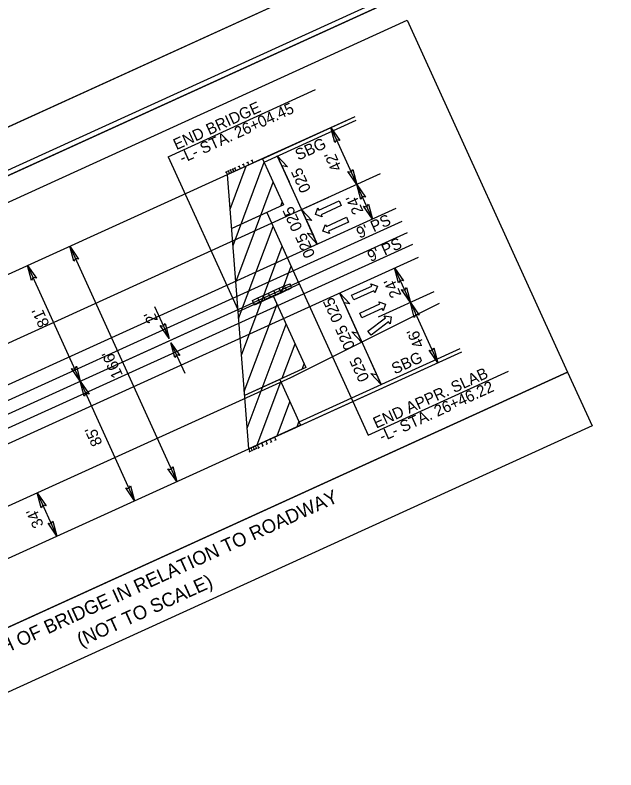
# Model space of a CAD drawing. Extents: x 2247864 to 2249896, y 662531 to 664296.
# Drawn here: x 2248887 to 2249194.5, y 663642.7 to 664028.8 of the extents above; entities that cross this region are included whole.
import ezdxf

# ---------------------------------------------------------------- set-up
doc = ezdxf.new("R2010")
doc.units = 0
for name, color, linetype in [('Prop Approach Slab', 7, 'Continuous'), ('Prop Approach Slab Hatching', 7, 'Continuous'), ('Prop Conc Barrier', 7, 'Continuous'), ('Prop Conc Shoulder Berm Gutter', 7, 'Continuous'), ('Prop Dimension', 7, 'Continuous'), ('Prop Dimension Text', 7, 'Continuous'), ('Prop EOT', 7, 'Continuous'), ('Prop Guardrail', 7, 'Continuous'), ('Prop Guardrail Attenuator CELL', 7, 'Continuous'), ('Prop Horizontal Alignment', 7, 'Continuous'), ('Prop Lane Arrow CELL', 7, 'Continuous'), ('Prop Lane Lines', 7, 'Continuous'), ('Prop Paved Shoulder', 7, 'Continuous'), ('Prop Roadway Bridge', 7, 'Continuous'), ('Prop Structure Anchor Unit CELL', 7, 'Continuous'), ('Prop Superelevation  Arrow CELL', 7, 'Continuous'), ('Prop Superelevation Label', 7, 'Continuous'), ('Prop Terminator CELL', 7, 'Continuous'), ('Sheet Clip Boundary CELL', 7, 'Continuous'), ('Sheet Cutting Line CELL', 7, 'Continuous'), ('Sheet Layout Plan Border', 7, 'Continuous'), ('Sheet Plan CELL', 7, 'Continuous'), ('Sheet Plan Layout CELL', 7, 'Continuous'), ('Sheet Plot Border Inside CELL', 7, 'Continuous'), ('Sheet Plot Border Outside CELL', 7, 'Continuous')]:
    doc.layers.add(name, color=color, linetype=linetype)

msp = doc.modelspace()

# ---------------------------------------------------------------- linework, layer by layer
at = {"layer": 'Prop Approach Slab'}
for p, q in [((2249013.7, 663955.37), (2248995.74, 663947.21)), ((2249013.66, 663955.35), (2249024.38, 663931.77)), ((2249024.38, 663931.77), (2248997.87, 663919.73)), ((2249015.83, 663927.89), (2248997.87, 663919.73)), ((2249015.83, 663927.89), (2249032.48, 663891.24)), ((2249032.48, 663891.24), (2249001.17, 663877.02)), ((2249019.14, 663885.18), (2249001.17, 663877.02)), ((2249019.14, 663885.18), (2249035.79, 663848.53)), ((2249035.79, 663848.53), (2249004.48, 663834.31)), ((2249022.45, 663842.47), (2249004.48, 663834.31)), ((2249022.45, 663842.47), (2249033.11, 663819)), ((2249033.11, 663819), (2249006.6, 663806.96))]:
    msp.add_line(p, q, dxfattribs=at)
at = {"layer": 'Prop Approach Slab Hatching'}
for p, q in [((2248998.55, 663910.88), (2249014.5, 663953.52)), ((2248997.11, 663929.55), (2249005.34, 663951.57)), ((2249000, 663892.21), (2249019.12, 663943.35)), ((2249022.98, 663931.13), (2249023.74, 663933.17)), ((2249001.44, 663873.55), (2249019.08, 663920.72)), ((2249002.89, 663854.88), (2249023.71, 663910.55)), ((2249023.36, 663887.1), (2249028.33, 663900.38)), ((2249004.34, 663836.21), (2249021.06, 663880.95)), ((2249005.78, 663817.55), (2249025.68, 663870.77)), ((2249023.75, 663843.07), (2249030.31, 663860.6)), ((2249033.9, 663847.68), (2249034.93, 663850.42)), ((2249010.99, 663808.95), (2249023.04, 663841.17)), ((2249021.14, 663813.56), (2249027.66, 663830.99)), ((2249031.3, 663818.17), (2249032.28, 663820.82))]:
    msp.add_line(p, q, dxfattribs=at)
at = {"layer": 'Prop Conc Barrier'}
msp.add_line((2248812.36, 663792.42), (2249009.02, 663881.76), dxfattribs=at)
at = {"layer": 'Prop Conc Shoulder Berm Gutter'}
for p, q in [((2249014.42, 663953.67), (2249061.56, 663975.15)), ((2249032.35, 663820.68), (2249114.82, 663858.27))]:
    msp.add_line(p, q, dxfattribs=at)
at = {"layer": 'Prop Dimension'}
for p, q in [((2249048.67, 663971.26), (2249061.88, 663942.18)), ((2249069.91, 663924.51), (2249061.88, 663942.18)), ((2248915.05, 663910.56), (2248969.73, 663790.2)), ((2248893.47, 663900.75), (2248920.39, 663841.5)), ((2249089.3, 663881.83), (2249081.27, 663899.49)), ((2248958.42, 663879.73), (2248965.81, 663863.46)), ((2249089.3, 663881.83), (2249103.35, 663850.9)), ((2249017.2, 663870.38), (2249017.21, 663870.38)), ((2248966.81, 663861.25), (2248973.93, 663845.59)), ((2248920.39, 663841.5), (2248948.14, 663780.4)), ((2249029.24, 663843.88), (2249029.25, 663843.88)), ((2248898.36, 663784.42), (2248908.39, 663762.34))]:
    msp.add_line(p, q, dxfattribs=at)
at = {"layer": 'Prop Dimension Text'}
for p, q in [((2248660.85, 663831.67), (2249087.72, 664026.19)), ((2249087.72, 664026.19), (2249169.78, 663846.12)), ((2248965.43, 663956.4), (2249040.76, 663990.73)), ((2248965.43, 663956.4), (2249001.09, 663878.15)), ((2249031.32, 663928.3), (2249047.63, 663935.73)), ((2249032.04, 663892.21), (2249067.69, 663813.97)), ((2249169.78, 663846.12), (2248742.91, 663651.6)), ((2249067.69, 663813.97), (2249139.51, 663846.69))]:
    msp.add_line(p, q, dxfattribs=at)
msp.add_lwpolyline([(2248742.91, 663651.6), (2249169.78, 663846.12), (2249182.27, 663818.71), (2248755.39, 663624.19)], close=True, dxfattribs=at)
at = {"layer": 'Prop EOT'}
for p, q in [((2248794.68, 663820.8), (2249074.06, 663947.71)), ((2248734.68, 663772.23), (2249082.11, 663930.06)), ((2248746.08, 663747.22), (2249093.51, 663905.04)), ((2249028.21, 663843.41), (2249104.25, 663881.48)), ((2248758.15, 663720.73), (2249028.21, 663843.41))]:
    msp.add_line(p, q, dxfattribs=at)
at = {"layer": 'Prop Guardrail'}
for p, q in [((2249060.82, 663976.77), (2249008.88, 663953.18)), ((2249019.75, 663812.93), (2249115.63, 663856.48))]:
    msp.add_line(p, q, dxfattribs=at)
at = {"layer": 'Prop Guardrail Attenuator CELL'}
for p, q in [((2249024.89, 663890.34), (2249025.8, 663890.75)), ((2249025.8, 663890.75), (2249027.73, 663891.35)), ((2249028.14, 663890.44), (2249027.73, 663891.35)), ((2249013.97, 663885.38), (2249016.7, 663886.62)), ((2249016.7, 663886.62), (2249019.43, 663887.86)), ((2249017.73, 663884.34), (2249016.7, 663886.62)), ((2249019.43, 663887.86), (2249022.16, 663889.1)), ((2249020.46, 663885.58), (2249019.43, 663887.86)), ((2249020.46, 663885.58), (2249023.19, 663886.82)), ((2249022.16, 663889.1), (2249024.89, 663890.34)), ((2249023.19, 663886.82), (2249022.16, 663889.1)), ((2249023.19, 663886.82), (2249025.93, 663888.07)), ((2249025.93, 663888.07), (2249024.89, 663890.34)), ((2249025.93, 663888.07), (2249026.84, 663888.48)), ((2249026.84, 663888.48), (2249028.55, 663889.53)), ((2249028.55, 663889.53), (2249028.14, 663890.44)), ((2249008.5, 663882.9), (2249011.24, 663884.14)), ((2249009.54, 663880.62), (2249008.5, 663882.9)), ((2249011.24, 663884.14), (2249013.97, 663885.38)), ((2249012.27, 663881.86), (2249011.24, 663884.14)), ((2249012.27, 663881.86), (2249015, 663883.1)), ((2249015, 663883.1), (2249013.97, 663885.38)), ((2249015, 663883.1), (2249017.73, 663884.34)), ((2249017.73, 663884.34), (2249020.46, 663885.58)), ((2249009.54, 663880.62), (2249012.27, 663881.86))]:
    msp.add_line(p, q, dxfattribs=at)
at = {"layer": 'Prop Horizontal Alignment'}
msp.add_line((2248740.38, 663759.73), (2249087.81, 663917.55), dxfattribs=at)
at = {"layer": 'Prop Lane Arrow CELL'}
for p, q in [((2249042.49, 663929.1), (2249052.79, 663933.8)), ((2249052.79, 663933.8), (2249053.89, 663931.37)), ((2249040.74, 663926.8), (2249041.98, 663930.21)), ((2249041.98, 663930.21), (2249042.49, 663929.1)), ((2249053.89, 663931.37), (2249043.59, 663926.68)), ((2249044.1, 663925.57), (2249040.74, 663926.8)), ((2249043.59, 663926.68), (2249044.1, 663925.57)), ((2249046.33, 663920.68), (2249056.63, 663925.37)), ((2249056.63, 663925.37), (2249057.73, 663922.95)), ((2249044.58, 663918.37), (2249045.82, 663921.78)), ((2249045.82, 663921.78), (2249046.33, 663920.68)), ((2249057.73, 663922.95), (2249047.43, 663918.25)), ((2249047.94, 663917.15), (2249044.58, 663918.37)), ((2249047.43, 663918.25), (2249047.94, 663917.15)), ((2249069.56, 663890.21), (2249069.06, 663891.31)), ((2249069.06, 663891.31), (2249072.42, 663890.09)), ((2249059.26, 663885.51), (2249069.56, 663890.21)), ((2249070.67, 663887.78), (2249060.37, 663883.09)), ((2249071.17, 663886.68), (2249070.67, 663887.78)), ((2249072.42, 663890.09), (2249071.17, 663886.68)), ((2249060.37, 663883.09), (2249059.26, 663885.51)), ((2249063.4, 663876.42), (2249073.7, 663881.12)), ((2249073.7, 663881.12), (2249073.2, 663882.22)), ((2249073.2, 663882.22), (2249076.56, 663881)), ((2249076.56, 663881), (2249075.31, 663877.58)), ((2249064.51, 663874), (2249063.4, 663876.42)), ((2249074.81, 663878.69), (2249064.51, 663874)), ((2249075.31, 663877.58), (2249074.81, 663878.69)), ((2249067.57, 663867.15), (2249076.58, 663873.99)), ((2249078.2, 663871.87), (2249069.18, 663865.03)), ((2249076.58, 663873.99), (2249075.85, 663874.96)), ((2249075.85, 663874.96), (2249079.4, 663874.5)), ((2249078.93, 663870.9), (2249078.2, 663871.87)), ((2249079.4, 663874.5), (2249078.93, 663870.9)), ((2249069.18, 663865.03), (2249067.57, 663867.15))]:
    msp.add_line(p, q, dxfattribs=at)
at = {"layer": 'Prop Lane Lines'}
msp.add_line((2249073.03, 663874.43), (2249101.55, 663887.38), dxfattribs=at)
at = {"layer": 'Prop Paved Shoulder'}
for p, q in [((2249013.66, 663955.35), (2249060.8, 663976.83)), ((2248737.69, 663765.61), (2249085.12, 663923.43)), ((2248743.07, 663753.84), (2249090.5, 663911.67)), ((2249025.01, 663815.32), (2249115.59, 663856.59))]:
    msp.add_line(p, q, dxfattribs=at)
at = {"layer": 'Prop Roadway Bridge'}
for p, q in [((2248815.39, 663865.29), (2248995.74, 663947.21)), ((2249006.6, 663806.96), (2248995.74, 663947.21)), ((2248826.26, 663725.03), (2249006.6, 663806.96))]:
    msp.add_line(p, q, dxfattribs=at)
at = {"layer": 'Prop Structure Anchor Unit CELL'}
for p, q in [((2248995.74, 663947.21), (2249008.88, 663953.18)), ((2249003.46, 663952.41), (2249004.26, 663952.77)), ((2249004.5, 663951.19), (2249003.86, 663952.59)), ((2249005.65, 663953.4), (2249006.46, 663953.77)), ((2249006.69, 663952.18), (2249006.05, 663953.59)), ((2249007.84, 663954.4), (2249008.65, 663954.76)), ((2249008.88, 663953.18), (2249008.24, 663954.58)), ((2248994.7, 663948.43), (2248995.5, 663948.79)), ((2248995.74, 663947.21), (2248995.1, 663948.61)), ((2248995.79, 663948.93), (2248996.6, 663949.29)), ((2248996.83, 663947.71), (2248996.2, 663949.11)), ((2248996.89, 663949.42), (2248997.69, 663949.79)), ((2248997.93, 663948.2), (2248997.29, 663949.61)), ((2248997.98, 663949.92), (2248998.79, 663950.29)), ((2248999.02, 663948.7), (2248998.39, 663950.1)), ((2248999.08, 663950.42), (2248999.88, 663950.78)), ((2249000.12, 663949.2), (2248999.48, 663950.6)), ((2249001.27, 663951.41), (2249002.07, 663951.78)), ((2249002.31, 663950.19), (2249001.67, 663951.6)), ((2249006.6, 663806.96), (2249019.75, 663812.93)), ((2249013.18, 663809.94), (2249013.81, 663808.54)), ((2249015.37, 663810.94), (2249016, 663809.53)), ((2249015.6, 663809.35), (2249016.4, 663809.72)), ((2249017.56, 663811.93), (2249018.19, 663810.53)), ((2249017.79, 663810.35), (2249018.6, 663810.71)), ((2249019.75, 663812.93), (2249020.38, 663811.52)), ((2249019.98, 663811.34), (2249020.79, 663811.71)), ((2249006.6, 663806.96), (2249007.24, 663805.55)), ((2249006.84, 663805.37), (2249007.64, 663805.74)), ((2249007.7, 663807.45), (2249008.34, 663806.05)), ((2249007.93, 663805.87), (2249008.74, 663806.23)), ((2249008.79, 663807.95), (2249009.43, 663806.55)), ((2249009.03, 663806.37), (2249009.83, 663806.73)), ((2249009.89, 663808.45), (2249010.53, 663807.05)), ((2249010.12, 663806.86), (2249010.93, 663807.23)), ((2249010.98, 663808.95), (2249011.62, 663807.54)), ((2249011.22, 663807.36), (2249012.02, 663807.73)), ((2249013.41, 663808.36), (2249014.21, 663808.72))]:
    msp.add_line(p, q, dxfattribs=at)
at = {"layer": 'Prop Superelevation  Arrow CELL'}
for p, q in [((2249021.19, 663956.76), (2249027.23, 663943.51)), ((2249033.64, 663929.36), (2249039.67, 663916.12)), ((2249041.66, 663911.69), (2249035.63, 663924.93)), ((2249053.06, 663886.68), (2249059.09, 663873.44)), ((2249064.64, 663861.19), (2249058.6, 663874.43)), ((2249074.34, 663839.82), (2249068.31, 663853.07))]:
    msp.add_line(p, q, dxfattribs=at)
for points in [[(2249021.19, 663956.76), (2249026.42, 663951.14), (2249023.52, 663951.65)], [(2249033.64, 663929.36), (2249038.86, 663923.74), (2249035.96, 663924.25)], [(2249041.66, 663911.69), (2249036.44, 663917.31), (2249039.34, 663916.8)], [(2249053.06, 663886.68), (2249058.28, 663881.06), (2249055.39, 663881.58)], [(2249064.64, 663861.19), (2249059.41, 663866.8), (2249062.31, 663866.29)], [(2249074.34, 663839.82), (2249069.12, 663845.44), (2249072.02, 663844.93)]]:
    msp.add_lwpolyline(points, close=True, dxfattribs=at)
at = {"layer": 'Prop Superelevation Label'}
for p, q in [((2249021.19, 663956.76), (2249041.66, 663911.69)), ((2249053.06, 663886.68), (2249074.34, 663839.82))]:
    msp.add_line(p, q, dxfattribs=at)
at = {"layer": 'Prop Terminator CELL'}
for points in [[(2249050.68, 663963.6), (2249048.67, 663971.26), (2249053.18, 663964.69), (2249051.5, 663965.03)], [(2249059.88, 663949.83), (2249061.88, 663942.18), (2249057.38, 663948.75), (2249059.05, 663948.41)], [(2249063.88, 663934.53), (2249061.88, 663942.18), (2249066.39, 663935.62), (2249064.71, 663935.95)], [(2249067.9, 663932.17), (2249069.91, 663924.51), (2249065.4, 663931.08), (2249067.08, 663930.75)], [(2248917.06, 663902.9), (2248915.05, 663910.56), (2248919.56, 663903.99), (2248917.88, 663904.33)], [(2248895.47, 663893.1), (2248893.47, 663900.75), (2248897.98, 663894.19), (2248896.3, 663894.52)], [(2249083.27, 663891.84), (2249081.27, 663899.49), (2249085.78, 663892.93), (2249084.1, 663893.26)], [(2249087.3, 663889.48), (2249089.3, 663881.83), (2249084.79, 663888.39), (2249086.47, 663888.06)], [(2249091.3, 663874.17), (2249089.3, 663881.83), (2249093.8, 663875.26), (2249092.13, 663875.6)], [(2248963.81, 663871.11), (2248965.81, 663863.46), (2248961.3, 663870.03), (2248962.98, 663869.69)], [(2248968.81, 663853.6), (2248966.81, 663861.25), (2248971.31, 663854.69), (2248969.64, 663855.02)], [(2249101.34, 663858.56), (2249103.35, 663850.9), (2249098.84, 663857.47), (2249100.52, 663857.13)], [(2248918.39, 663849.15), (2248920.39, 663841.5), (2248915.89, 663848.06), (2248917.56, 663847.73)], [(2248922.39, 663833.84), (2248920.39, 663841.5), (2248924.89, 663834.93), (2248923.22, 663835.27)], [(2248967.72, 663797.86), (2248969.73, 663790.2), (2248965.22, 663796.77), (2248966.89, 663796.43)], [(2248946.14, 663788.05), (2248948.14, 663780.4), (2248943.64, 663786.96), (2248945.31, 663786.63)], [(2248900.36, 663776.77), (2248898.36, 663784.42), (2248902.86, 663777.86), (2248901.19, 663778.19)], [(2248906.39, 663769.99), (2248908.39, 663762.34), (2248903.88, 663768.91), (2248905.56, 663768.57)]]:
    msp.add_lwpolyline(points, close=True, dxfattribs=at)
at = {"layer": 'Sheet Clip Boundary CELL'}
msp.add_lwpolyline([(2248241.67, 663371.06), (2248514.44, 662770.57), (2248551.22, 662641.58), (2249564.56, 663103.35), (2249531.17, 663176.64), (2249788.88, 663294.08), (2249780.68, 663312.06), (2249743.43, 663294.89), (2249677.44, 663353.62), (2249425.27, 663908.72), (2249477.5, 663985.14), (2249305.27, 663906.66), (2249217.58, 664099.11), (2248115.83, 663597.06)], close=True, dxfattribs=at)
at = {"layer": 'Sheet Cutting Line CELL'}
msp.add_line((2249441.45, 664225.83), (2247909.5, 663527.75), dxfattribs=at)
at = {"layer": 'Sheet Layout Plan Border'}
msp.add_lwpolyline([(2248198.13, 663481.51), (2248575.77, 662652.77), (2249849.75, 663233.3), (2249502.05, 663996.33), (2249329.83, 663917.85), (2249242.13, 664110.3), (2248140.38, 663608.25)], close=True, dxfattribs=at)
at = {"layer": 'Sheet Plan CELL'}
for points in [[(2249435.32, 664198.33), (2248070.33, 663576.33), (2248505.72, 662620.85), (2249870.7, 663242.85)], [(2248505.72, 662620.85), (2248070.31, 663576.29), (2249253.26, 664115.38), (2249315.49, 663978.83), (2249497.53, 664061.77), (2249870.7, 663242.85)]]:
    msp.add_lwpolyline(points, close=True, dxfattribs=at)
at = {"layer": 'Sheet Plan Layout CELL'}
msp.add_lwpolyline([(2248070.31, 663576.29), (2248505.72, 662620.85), (2249870.68, 663242.84), (2249522.99, 664005.87), (2249305.27, 663906.66), (2249217.58, 664099.11)], close=True, dxfattribs=at)
at = {"layer": 'Sheet Plot Border Inside CELL'}
msp.add_lwpolyline([(2248367.09, 662554.92), (2249883.1, 663245.75), (2249445.65, 664205.77), (2247929.62, 663514.94)], close=True, dxfattribs=at)
at = {"layer": 'Sheet Plot Border Outside CELL'}
msp.add_lwpolyline([(2248363.56, 662531.33), (2249895.5, 663229.41), (2249441.45, 664225.83), (2247909.5, 663527.75)], close=True, dxfattribs=at)

# ---------------------------------------------------------------- texts
at = {"layer": 'Prop Dimension Text'}
for s, height, rotation, p in [('END BRIDGE', 5.775, 24.4979, (2248969.6, 663959.68)), ('-L- STA. 26+04.45', 5.775, 24.4979, (2248972.72, 663952.85)), ('SBG', 5.775, 24.4979, (2249031.96, 663954.35)), ("42'", 5.775, 114.4301, (2249054.43, 663950.44)), ("24'", 5.775, 114.4301, (2249065.44, 663928.4)), ("9' PS", 5.775, 24.4301, (2249063.31, 663914.41)), ("9' PS", 5.775, 24.4301, (2249068.95, 663902.44)), ("24'", 5.775, 114.4301, (2249084.85, 663885.71)), ("81'", 5.775, 114.4301, (2248904.74, 663870.66)), ("2'", 5.775, 114.4301, (2248960.29, 663872.7)), ("46'", 5.775, 114.4301, (2249096.57, 663860.07)), ('SBG', 5.775, 24.4979, (2249081.3, 663844.94)), ("166'", 5.775, 114.4301, (2248942.32, 663844.67)), ('END APPR. SLAB', 5.775, 24.4979, (2249071.86, 663817.24)), ('-L- STA. 26+46.22', 5.775, 24.4979, (2249074.98, 663810.41)), ("85'", 5.775, 114.4301, (2248931.87, 663809.79)), ('SKETCH OF BRIDGE IN RELATION TO ROADWAY', 7, 24.4979, (2248852.72, 663688.74)), ("34'", 5.775, 114.4301, (2248901.84, 663767.99)), ('(NOT TO SCALE)', 7, 24.4979, (2248920.7, 663705.59))]:
    msp.add_text(s, height=height, rotation=rotation, dxfattribs=at).set_placement(p)
at = {"layer": 'Prop Superelevation Label'}
for p in [(2249038.58, 663939.58), (2249034.23, 663919.84), (2249040.74, 663906.19), (2249054.94, 663873.23), (2249061.16, 663859.13), (2249068.48, 663842.85)]:
    msp.add_text('025', height=5.775, rotation=114.4979, dxfattribs=at).set_placement(p)

doc.saveas('drawing.dxf')
